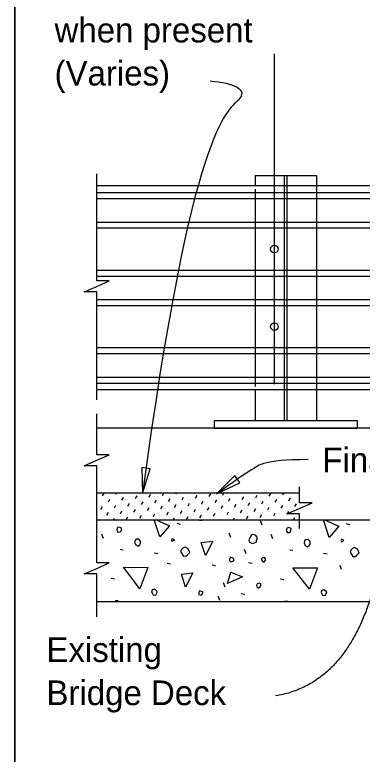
# Model space of a CAD drawing. Extents: x 0 to 41.1, y 0 to 25.9.
# Drawn here: x 0 to 2.84, y 4.8 to 10.84 of the extents above; entities that cross this region are included whole.
import ezdxf

# ---------------------------------------------------------------- set-up
doc = ezdxf.new("R2010")
doc.units = 0
for name, color, linetype in [('Dimension', 7, 'Continuous'), ('ExistSuperStruct', 7, 'Continuous'), ('Miscellaneous', 7, 'Continuous'), ('Miscellaneous1', 7, 'Continuous'), ('SteelMisc', 7, 'Continuous'), ('SteelMisc_h', 7, 'Continuous'), ('TextStructures', 7, 'Continuous')]:
    doc.layers.add(name, color=color, linetype=linetype)

msp = doc.modelspace()

# ---------------------------------------------------------------- linework, layer by layer
at = {"layer": 'Dimension'}
msp.add_line((2.1218, 7.8171), (2.1218, 10.5177), dxfattribs=at)
for points in [[(0.6692, 7.6894), (0.6692, 8.5726), (0.5659, 8.5726), (0.6692, 8.6176), (0.7725, 8.6626), (0.6692, 8.6626), (0.6692, 9.5356)], [(0.6692, 6.682), (0.6692, 7.152), (0.5659, 7.152), (0.6692, 7.197), (0.7725, 7.242), (0.6692, 7.242), (0.6692, 7.5765)], [(2.3272, 6.638), (2.3272, 6.7588), (2.2238, 6.7588), (2.3272, 6.8038), (2.4305, 6.8488), (2.3272, 6.8488), (2.3272, 6.9794)], [(0.6692, 5.9169), (0.6692, 6.2675), (0.5659, 6.2675), (0.6692, 6.3125), (0.7725, 6.3575), (0.6692, 6.3575), (0.6692, 6.682)]]:
    msp.add_lwpolyline(points, dxfattribs=at)
for points in [[(1.0445, 6.9254), (1.107, 7.1272), (1.0371, 7.1365)], [(1.6487, 6.9223), (1.8393, 7.0133), (1.7986, 7.071)]]:
    msp.add_lwpolyline(points, close=True, dxfattribs=at)
for points, degree in [([(1.5957, 10.2963), (1.793, 10.2775), (2.0322, 10.1799), (1.4442, 9.9184), (1.0445, 6.9254)], 3), ([(2.3972, 7.2025), (2.2038, 7.2005), (2.0154, 7.18), (1.944, 7.1303), (1.6486, 6.9223)], 3), ([(2.9644, 6.2731), (2.7489, 5.3695), (2.13, 5.2717)], 2)]:
    msp.add_open_spline(points, degree=degree, dxfattribs=at)
at = {"layer": 'ExistSuperStruct'}
for p, q in [((6.8429, 7.4599), (0.6692, 7.4599)), ((2.3271, 6.9289), (0.6692, 6.9289)), ((0.6692, 6.71), (6.8429, 6.71)), ((0.6692, 6.0432), (6.8429, 6.0432))]:
    msp.add_line(p, q, dxfattribs=at)
at = {"layer": 'Miscellaneous'}
for p, q in [((0.7161, 6.9064), (0.729, 6.9288)), ((0.8267, 6.9193), (0.8322, 6.9289)), ((0.8755, 6.8705), (0.8885, 6.8929)), ((0.9862, 6.8835), (0.9991, 6.9059)), ((1.0968, 6.8964), (1.1098, 6.9188)), ((1.2074, 6.9094), (1.2187, 6.9289)), ((1.3181, 6.9224), (1.3218, 6.9289)), ((1.3669, 6.8735), (1.3799, 6.8959)), ((1.4775, 6.8865), (1.4905, 6.9089)), ((1.5882, 6.8995), (1.6011, 6.9218)), ((1.6988, 6.9124), (1.7083, 6.9289)), ((1.8094, 6.9254), (1.8115, 6.9289)), ((1.8583, 6.8765), (1.8712, 6.8989)), ((1.9689, 6.8895), (1.9819, 6.9119)), ((2.0795, 6.9025), (2.0925, 6.9249)), ((2.1902, 6.9154), (2.1979, 6.9289)), ((2.239, 6.8666), (2.252, 6.889)), ((2.3008, 6.9284), (2.3011, 6.9289)), ((0.7649, 6.8575), (0.7779, 6.8799)), ((0.8137, 6.8087), (0.8267, 6.8311)), ((0.9244, 6.8217), (0.9373, 6.8441)), ((1.035, 6.8346), (1.048, 6.857)), ((1.1456, 6.8476), (1.1586, 6.87)), ((1.2563, 6.8606), (1.2692, 6.883)), ((1.3051, 6.8117), (1.3181, 6.8341)), ((1.4157, 6.8247), (1.4287, 6.8471)), ((1.5264, 6.8377), (1.5393, 6.86)), ((1.637, 6.8506), (1.65, 6.873)), ((1.7476, 6.8636), (1.7606, 6.886)), ((1.7965, 6.8147), (1.8094, 6.8371)), ((1.9071, 6.8277), (1.9201, 6.8501)), ((2.0177, 6.8407), (2.0307, 6.8631)), ((2.1284, 6.8536), (2.1413, 6.876)), ((2.1772, 6.8048), (2.1902, 6.8272)), ((2.2878, 6.8178), (2.3008, 6.8402)), ((0.7031, 6.7957), (0.7161, 6.8181)), ((0.7519, 6.7469), (0.7649, 6.7693)), ((0.8626, 6.7599), (0.8755, 6.7823)), ((0.9732, 6.7728), (0.9862, 6.7952)), ((1.0838, 6.7858), (1.0968, 6.8082)), ((1.1945, 6.7988), (1.2074, 6.8212)), ((1.2433, 6.7499), (1.2563, 6.7723)), ((1.3539, 6.7629), (1.3669, 6.7853)), ((1.4646, 6.7759), (1.4775, 6.7982)), ((1.5752, 6.7888), (1.5882, 6.8112)), ((1.6858, 6.8018), (1.6988, 6.8242)), ((1.7347, 6.7529), (1.7476, 6.7753)), ((1.8453, 6.7659), (1.8583, 6.7883)), ((1.9559, 6.7789), (1.9689, 6.8013)), ((2.0666, 6.7918), (2.0795, 6.8142)), ((2.226, 6.756), (2.239, 6.7784)), ((2.3367, 6.7689), (2.3368, 6.7691)), ((0.8076, 6.7099), (0.8137, 6.7205)), ((0.9114, 6.711), (0.9244, 6.7334)), ((1.022, 6.724), (1.035, 6.7464)), ((1.1327, 6.737), (1.1456, 6.7594)), ((1.1941, 6.7099), (1.1945, 6.7105)), ((1.2972, 6.7099), (1.3051, 6.7235)), ((1.4028, 6.7141), (1.4157, 6.7364)), ((1.5134, 6.727), (1.5264, 6.7494)), ((1.624, 6.74), (1.637, 6.7624)), ((1.6837, 6.7099), (1.6858, 6.7135)), ((1.7869, 6.7099), (1.7965, 6.7265)), ((1.8941, 6.7171), (1.9071, 6.7395)), ((2.0048, 6.73), (2.0177, 6.7524)), ((2.1154, 6.743), (2.1284, 6.7654)), ((2.1733, 6.7099), (2.1772, 6.7166)), ((2.2765, 6.7099), (2.2878, 6.7295)), ((1.3228, 6.6827), (1.351, 6.6757)), ((2.021, 6.6668), (2.0069, 6.7022)), ((2.7074, 6.6792), (2.7357, 6.6721)), ((0.7241, 6.5578), (0.71, 6.5932)), ((1.7647, 6.5661), (1.7506, 6.6014)), ((2.1088, 6.5543), (2.0946, 6.5897)), ((0.862, 6.4695), (0.8867, 6.4659)), ((1.8902, 6.4335), (1.8778, 6.4671)), ((2.2467, 6.4659), (2.2714, 6.4624)), ((1.1378, 6.4412), (1.1678, 6.4359)), ((2.5224, 6.4376), (2.5525, 6.4323)), ((1.2447, 6.3573), (1.273, 6.3502)), ((1.6127, 6.3433), (1.6409, 6.3362)), ((1.909, 6.3616), (1.9391, 6.3563)), ((2.6709, 6.3033), (2.6586, 6.3369)), ((0.7877, 6.2326), (0.8143, 6.2273)), ((2.1724, 6.229), (2.1989, 6.2237)), ((1.7187, 6.1607), (1.7064, 6.1943)), ((1.8489, 6.1071), (1.8807, 6.1035)), ((1.6763, 6.0511), (1.6622, 6.0865))]:
    msp.add_line(p, q, dxfattribs=at)
for points in [[(1.1855, 6.5702), (1.1401, 6.7099)], [(1.1539, 6.7099), (1.2633, 6.6621), (1.1855, 6.5702)], [(1.5091, 6.7099), (1.5101, 6.7075), (1.5077, 6.7099)], [(1.5101, 6.7075), (1.5313, 6.7075), (1.5338, 6.7099)], [(2.5702, 6.5667), (2.5236, 6.7099)], [(2.5305, 6.7099), (2.648, 6.6586), (2.5702, 6.5667)], [(0.8337, 6.625), (0.8425, 6.6091), (0.862, 6.6109), (0.8708, 6.6233), (0.8726, 6.6427), (0.8602, 6.648), (0.8514, 6.6498), (0.8408, 6.6462), (0.8372, 6.6427), (0.8337, 6.625)], [(2.2184, 6.6215), (2.2272, 6.6056), (2.2467, 6.6073), (2.2555, 6.6197), (2.2573, 6.6392), (2.2449, 6.6445), (2.2361, 6.6462), (2.2255, 6.6427), (2.2219, 6.6392), (2.2184, 6.6215)], [(1.9185, 6.5289), (1.9415, 6.5166), (1.9715, 6.5289), (1.9839, 6.5661), (1.9662, 6.5837), (1.9432, 6.589), (1.9326, 6.582), (1.9203, 6.5625), (1.9114, 6.5466), (1.9185, 6.5289)], [(0.9787, 6.526), (0.9893, 6.5048), (1.0069, 6.4942), (1.0211, 6.5048), (1.0282, 6.5154), (1.0282, 6.5366), (1.0123, 6.5525), (0.9928, 6.5508), (0.984, 6.5419), (0.9787, 6.526)], [(1.2845, 6.5349), (1.3039, 6.5437), (1.2969, 6.5508), (1.2845, 6.5561), (1.2792, 6.5437), (1.2845, 6.5349)], [(1.5579, 6.4193), (1.5243, 6.5236), (1.618, 6.536), (1.5579, 6.4193)], [(2.3633, 6.5225), (2.3739, 6.5013), (2.3916, 6.4907), (2.4058, 6.5013), (2.4128, 6.5119), (2.4128, 6.5331), (2.3969, 6.549), (2.3775, 6.5472), (2.3686, 6.5384), (2.3633, 6.5225)], [(2.6692, 6.5313), (2.6886, 6.5402), (2.6815, 6.5472), (2.6692, 6.5525), (2.6639, 6.5402), (2.6692, 6.5313)], [(1.3552, 6.45), (1.3782, 6.4129), (1.4012, 6.4147), (1.41, 6.4235), (1.4294, 6.4429), (1.4171, 6.473), (1.3923, 6.4871), (1.3746, 6.4801), (1.3605, 6.4659), (1.3552, 6.45)], [(2.7399, 6.4465), (2.7629, 6.4094), (2.7858, 6.4111), (2.7947, 6.42), (2.8141, 6.4394), (2.8017, 6.4695), (2.777, 6.4836), (2.7593, 6.4765), (2.7452, 6.4624), (2.7399, 6.4465)], [(1.7636, 6.3704), (1.776, 6.3686), (1.7883, 6.3739), (1.7919, 6.3845), (1.7866, 6.3933), (1.776, 6.4004), (1.7636, 6.4057), (1.7565, 6.3916), (1.753, 6.381), (1.7636, 6.3704)], [(2.0204, 6.374), (2.031, 6.3634), (2.0416, 6.3705), (2.0487, 6.3811), (2.0451, 6.3987), (2.0363, 6.4005), (2.0239, 6.3987), (2.0133, 6.3881), (2.0204, 6.374)], [(1.0229, 6.146), (0.8885, 6.3227), (1.0883, 6.321), (1.0229, 6.146)], [(2.4075, 6.1424), (2.2732, 6.3192), (2.4729, 6.3174), (2.4075, 6.1424)], [(1.3946, 6.1611), (1.361, 6.2654), (1.4547, 6.2778), (1.3946, 6.1611)], [(1.7376, 6.1902), (1.7658, 6.2821), (1.8595, 6.245), (1.7376, 6.1902)], [(1.985, 6.1548), (1.9921, 6.1548), (2.0063, 6.1619), (2.0116, 6.1778), (2.0098, 6.1866), (1.9956, 6.1937), (1.978, 6.1831), (1.9744, 6.1725), (1.978, 6.1619), (1.985, 6.1548)], [(1.1219, 6.1141), (1.1307, 6.0982), (1.1519, 6.0947), (1.1607, 6.1106), (1.1643, 6.1247), (1.1554, 6.1336), (1.1395, 6.1424), (1.1236, 6.1371), (1.1183, 6.1212), (1.1219, 6.1141)], [(1.5027, 6.1012), (1.5222, 6.0958), (1.5345, 6.1047), (1.5363, 6.1171), (1.5328, 6.1206), (1.5186, 6.1277), (1.5063, 6.1259), (1.5045, 6.1135), (1.5027, 6.1012)], [(2.5065, 6.1106), (2.5154, 6.0947), (2.5366, 6.0912), (2.5454, 6.1071), (2.549, 6.1212), (2.5401, 6.13), (2.5242, 6.1389), (2.5083, 6.1336), (2.503, 6.1177), (2.5065, 6.1106)], [(0.8471, 6.0432), (0.8461, 6.047), (0.8231, 6.0487), (0.8213, 6.0432)], [(2.2308, 6.0432), (2.2308, 6.0434), (2.2078, 6.0452), (2.2071, 6.0432)]]:
    msp.add_lwpolyline(points, dxfattribs=at)
at = {"layer": 'Miscellaneous1'}
msp.add_lwpolyline([(0, 25.9461), (41.0506, 25.9461), (41.0506, 0), (0, 0)], close=True, dxfattribs=at)
at = {"layer": 'SteelMisc'}
for p, q in [((1.9655, 9.5225), (2.4655, 9.5225)), ((1.9655, 9.5225), (1.9655, 9.4391)), ((2.4655, 9.5225), (2.4655, 9.4391)), ((12.7651, 9.4391), (0.6692, 9.4391)), ((0.6692, 9.3835), (12.7651, 9.3835)), ((0.6692, 9.3353), (12.7651, 9.3353)), ((0.6692, 9.1425), (12.7651, 9.1425)), ((0.6692, 9.0943), (12.7651, 9.0943)), ((0.6692, 8.7503), (12.7651, 8.7503)), ((0.6692, 8.7021), (12.7651, 8.7021)), ((0.6692, 8.5093), (12.7651, 8.5093)), ((0.6692, 8.4611), (12.7651, 8.4611)), ((0.6692, 8.1172), (12.7651, 8.1172)), ((0.6692, 8.069), (12.7651, 8.069)), ((0.6692, 7.8761), (12.7651, 7.8761)), ((0.6692, 7.8279), (12.7651, 7.8279)), ((12.7651, 7.7724), (0.6692, 7.7724)), ((1.9655, 7.7725), (1.9655, 7.5225)), ((2.4655, 7.7724), (2.4655, 7.5225)), ((1.6322, 7.5225), (2.7988, 7.5225)), ((1.6322, 7.46), (1.6322, 7.5225)), ((1.9655, 7.5225), (2.4655, 7.5225)), ((2.7988, 7.5225), (2.7988, 7.46)), ((1.6322, 7.46), (2.7988, 7.46))]:
    msp.add_line(p, q, dxfattribs=at)
for centre in [(2.1218, 8.9224), (2.1218, 8.2892)]:
    msp.add_circle(centre, 0.0312, dxfattribs=at)
at = {"layer": 'SteelMisc_h'}
for p, q in [((2.2051, 7.5225), (2.2051, 9.5225)), ((2.2259, 7.5225), (2.2259, 9.5225)), ((2.4655, 9.4391), (2.4655, 7.7724)), ((1.9655, 9.4106), (1.9655, 7.7987))]:
    msp.add_line(p, q, dxfattribs=at)
at = {"layer": 'TextStructures'}
msp.add_lwpolyline([(0, 0), (41.0506, 0), (41.0506, 25.9461), (0, 25.9461)], close=True, dxfattribs=at)

# ---------------------------------------------------------------- texts
at = {"layer": 'Dimension'}
for s, p in [('when present', (0.325, 10.6104)), ('(Varies)', (0.325, 10.2584)), ('Existing ', (0.2585, 5.5481)), ('Bridge Deck', (0.2585, 5.1961))]:
    msp.add_text(s, height=0.2016, dxfattribs=at).set_placement(p)
at = {"layer": 'TextStructures'}
msp.add_text('Final Riding Surface', height=0.2016, dxfattribs=at).set_placement((2.5134, 7.0989))

doc.saveas('drawing.dxf')
